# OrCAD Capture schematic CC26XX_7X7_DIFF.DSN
size A3; title: CC2650EM-7ID; rev: 1.2.6
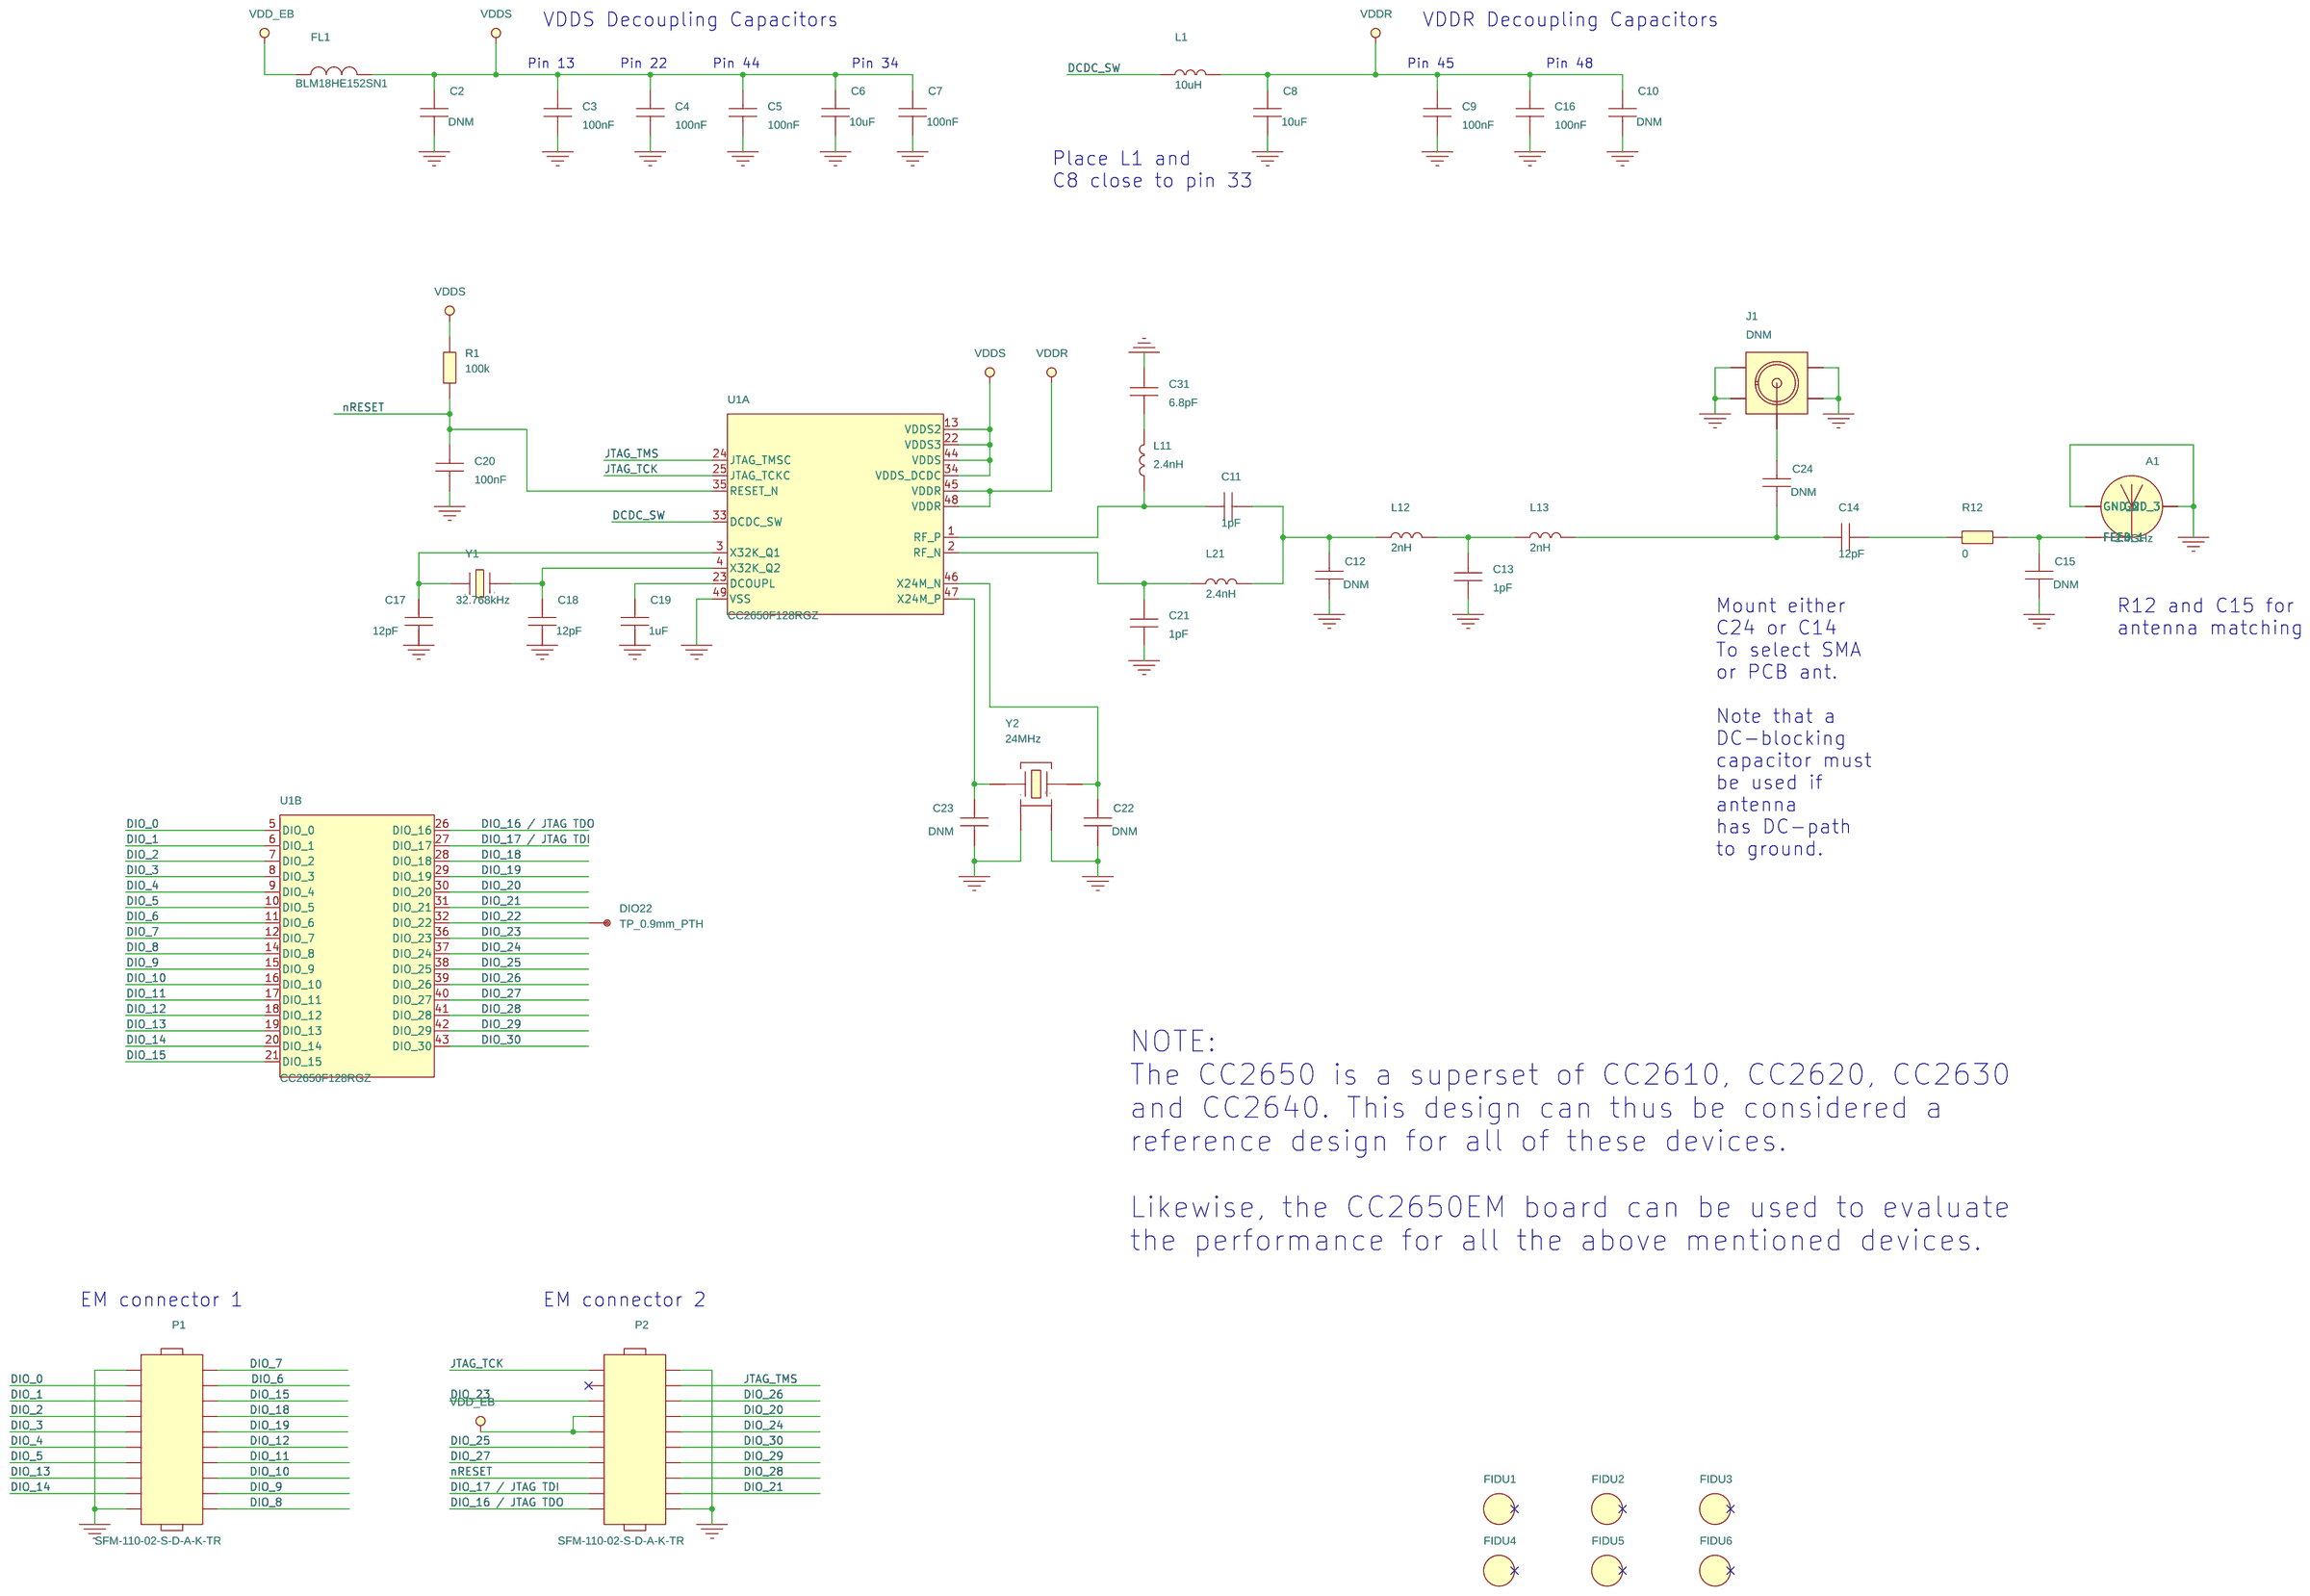
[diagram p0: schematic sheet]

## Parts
A1  2.4GHz  [ANTENNA_DN007AN]
C2  DNM  [CAPC1608X90L]
C3  100nF  [CAPC1005X60L]
C4  100nF  [CAPC1005X60L]
C5  100nF  [CAPC1005X60L]
C6  10uF  [CAPC1608X90N]
C7  100nF  [CAPC1608X90L]
C8  10uF  [CAPC1608X90N]
C9  100nF  [CAPC1005X60L]
C10  DNM  [CAPC1005X60L]
C11  1pF  [CAPC1005X60L]
C12  DNM  [CAPC1005X60L]
C13  1pF  [CAPC1005X60L]
C14  12pF  [CAPC1005X60L]
C15  DNM  [CAPC1005X60L]
C16  100nF  [CAPC1005X60L]
C17  12pF  [CAPC1005X60L]
C18  12pF  [CAPC1005X60L]
C19  1uF  [CAPC1005X60L]
C20  100nF  [CAPC1005X60L]
C21  1pF  [CAPC1005X60L]
C22  DNM  [CAPC1005X60L]
C23  DNM  [CAPC1005X60L]
C24  DNM  [CAPC1005X60L]
C31  6.8pF  [CAPC1005X60L]
DIO22  TP_0.9mm_PTH  [TP150_90H]
FIDU1  FIDU_1MM  [FID100X115]
FIDU2  FIDU_1MM  [FID100X115]
FIDU3  FIDU_1MM  [FID100X115]
FIDU4  FIDU_1MM  [FID100X115]
FIDU5  FIDU_1MM  [FID100X115]
FIDU6  FIDU_1MM  [FID100X115]
FL1  BLM18HE152SN1  [FIL_BLM18HE152SN1DL]
J1  DNM  [HUSTSAN_SMA10V21TGGAN]
L1  10uH  [INDC2012X150L]
L11  2.4nH  [INDC1005X60L]
L12  2nH  [INDC1005X60L]
L13  2nH  [INDC1005X60L]
L21  2.4nH  [INDC1005X60L]
P1  SFM-110-02-S-D-A-K-TR  [SAMTEC_SFM11002AN]
P2  SFM-110-02-S-D-A-K-TR  [SAMTEC_SFM11002AN]
R1  100k  [RESC1005X40L]
R12  0  [RESC1005X40L]
U1  CC2650F128RGZ  [QFNFC50P700X700X80-49CL]  (sections A,B)
Y1  32.768kHz  [XTAL_FC-135N]
Y2  24MHz  [OSCCC250X320X60-4L]

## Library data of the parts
A1 = ANTENNA_DN007: MECHANIC, 2.4GHz INVERTED F ANTENNA, SMD; AutoDoc File: http://notefied-dynamic-precision.com/DB/Apps/Desktop/Item/Object.aspx?id=85542; Budget Currency: N/A; Budget Price: N/A; Datasheet URL 1: http://www.ti.com/lit/er/swrz002d/swrz002d.pdf; Datasheet URL 2: http://www.ti.com/lit/ds/symlink/cc2500.pdf; Definied Quality: INDUSTRIAL; Esd Level: HBM 500V; FPLIST: ANTENNA_DN007N,ANTENNA_DN007AN,; Last Time Buy: N/A; Lead Time: N/A; MPN: DN007; MPN Status: ACTIVE; MSL: N/A; MTBF: N/A; MTBF Standard: N/A; Manufacturer: TEXAS INSTRUMENTS; Max Oper Temp: +85DEGC; Min Oper Temp: -40DEGC; Mounting Type: SMD; NOTE Status: PREFERRED; Old Footprint: ANTENNA_DN007N,ANTENNA_DN007AN; Packing Size: N/A; Packing Type: N/A; Part Number: 13-00347; Part Type: MECHANIC\ANTENNA; Revision: R006; RoHS Status: LEADED; WEIGHT: N/A
C2 = CAPACITOR: CAPACITOR, DO NOT MOUNT, 0603, SMD; ALT_SYMBOLS: CAPC1608X90L,CAPC1608X90M; AutoDoc File: http://notefied-dynamic-precision.com/DB/Apps/Desktop/Item/Object.aspx?id=50475; FPLIST: CAPC1608X90N,CAPC1608X90L,CAPC1608X90M; Old Footprint: CAPC1608X90N,0603; Part Number: 02-01324; Part Type: CAPACITOR\CERAMIC\0603; Revision: R003
C3-C5 C9 C16 C20 = CAPACITOR: CAPACITOR, CERAMIC X7R, 100nF, 6.3V, -10%/+10%, -55DEGC/+125DEGC, 0402, SMD; ALT_SYMBOLS: CAPC1005X60L,CAPC1005X60M; AutoDoc File: http://notefied-dynamic-precision.com/DB/Apps/Desktop/Item/Object.aspx?id=73748; Budget Currency: EUR; Budget Price: 0.003; Datasheet URL 1: http://search.murata.co.jp/Ceramy/image/img/A01X/G101/ENG/GRM155R70J104KA01-01.pdf; Datasheet URL 2: http://search.murata.co.jp/Ceramy/image/img/A01X/G101/ENG/GRM155R70J104KA01-01.pdf; Dielectric Type: X7R; FPLIST: CAPC1005X60N,CAPC1005X60L,CAPC1005X60M; Lead Time: 10; LifeCycle Status: ACTIVE; MPN: GRM155R70J104KA01D; MPN Status: ACTIVE; Manufacturer: MURATA; Max Oper Temp: +125DEGC; Max Tol: +10%; Min Oper Temp: -55DEGC; Min Tol: -10%; Mounting Type: SMD; NOTE Status: PREFERRED; Old Footprint: CAPC1005X60N,0402; PCB Package: 0402; Packing Size: 10000; Packing Type: TAPE_&_REEL; Part Number: 02-02323; Part Type: CAPACITOR\CERAMIC\0402; Revision: R000; RoHS Status: ROHS_COMPLIANT; Rtd Voltage: 6.3V; WEIGHT: 0.0016g
C6 C8 = CAPACITOR: CAPACITOR, CERAMIC X5R, 10uF, 6.3V, -20%/+20%, -55DEGC/+85DEGC, 0603, SMD; ALT_SYMBOLS: CAPC1608X90L,CAPC1608X90M; AutoDoc File: http://notefied-dynamic-precision.com/DB/Apps/Desktop/Item/Object.aspx?id=74686; Budget Currency: EUR; Budget Price: 0.067; Datasheet URL 1: http://search.murata.co.jp/Ceramy/image/img/w_hinm/L0005E.pdf; Datasheet URL 2: http://psearch.murata.com/capacitor/product/GRM188R60J106ME47%23.pdf; Definied Quality: INDUSTRIAL; Dielectric Type: X5R; Esd Level: N/A; FPLIST: CAPC1608X90N,CAPC1608X90L,CAPC1608X90M; Last Time Buy: N/A; Lead Time: 20; MPN: GRM188R60J106ME47D; MPN Status: NRND; MSL: 1; MTBF: N/A; MTBF Standard: N/A; Manufacturer: MURATA; Max Oper Temp: +85DEGC; Max Tol: +20%; Min Oper Temp: -55DEGC; Min Tol: -20%; Mounting Type: SMD; NOTE Status: PREFERRED; PCB Package: 0603; Packing Size: 4000; Packing Type: TAPE_&_REEL; Part Number: 02-02419; Part Type: CAPACITOR\CERAMIC\0603; Revision: R003; RoHS Status: ROHS_COMPLIANT; Rtd Voltage: 6.3V; WEIGHT: 0.0063g
C7 = CAPACITOR: CAPACITOR, CERAMIC X7R, 100nF, 25V, -10%/+10%, -55DEGC/+125DEGC, 0603, SMD; ALT_SYMBOLS: CAPC1608X90L,CAPC1608X90M; AutoDoc File: http://notefied-dynamic-precision.com/DB/Apps/Desktop/Item/Object.aspx?id=72070; Budget Currency: N/A; Budget Price: 0.00391; Cage Code: C0151; Datasheet URL 1: http://search.murata.co.jp/Ceramy/image/img/A01X/G101/ENG/GRM188R71E104KA01-01.pdf; Datasheet URL 2: http://search.murata.co.jp/Ceramy/image/img/A01X/G101/ENG/GRM188R71E104KA01-01.pdf; Dielectric Type: X7R; FPLIST: CAPC1608X90N,CAPC1608X90L,CAPC1608X90M; MPN: GRM188R71E104KA01D; MPN Status: ACTIVE; Manufacturer: MURATA; Max Oper Temp: +125DEGC; Max Tol: +10%; Min Oper Temp: -55DEGC; Min Tol: -10%; Mounting Type: SMD; NOTE Status: PREFERRED; Old Footprint: CAPC1608X90N,0603; PCB Package: 0603; Packing Size: 4000; Packing Type: TAPE_&_REEL; Part Number: 02-01992; Part Type: CAPACITOR\CERAMIC\0603; Revision: R000; RoHS Status: ROHS_COMPLIANT; Rtd Voltage: 25V; WEIGHT: 0.0063g
C10 C12 C15 C22-C24 = CAPACITOR: CAPACITOR, CERAMIC, N/A VALUE, -55DEGC/+125DEGC, 0402, SMD; ALT_SYMBOLS: CAPC1005X60L,CAPC1005X60M; AutoDoc File: http://notefied-dynamic-precision.com/DB/Apps/Desktop/Item/Object.aspx?id=84862; Budget Currency: USD; Budget Price: 0.00589; FPLIST: CAPC1005X60N,CAPC1005X60L,CAPC1005X60M; MPN: CAPACITOR_0402_DNM_N/A_M; MPN Status: ACTIVE; Manufacturer: Manufacturer selection; Max Oper Temp: +125DEGC; Min Oper Temp: -55DEGC; Mounting Type: SMD; NOTE Status: PREFERRED; Old Footprint: CAPC1005X60N; PCB Package: 0402; Packing Size: 10000; Packing Type: TAPE_&_REEL; Part Number: 02-04164; Part Type: CAPACITOR\CERAMIC\0402; Revision: R000; RoHS Status: PART NOT KNOWN
C11 C13 C21 = CAPACITOR: CAPACITOR, CERAMIC C0G/NP0, 1pF, 50V, -0.25pF/ +0.25pF, -55DEGC/+125DEGC, 0402, SMD; ALT_SYMBOLS: CAPC1005X60L,CAPC1005X60M; AutoDoc File: http://notefied-dynamic-precision.com/DB/Apps/Desktop/Item/Object.aspx?id=87790; Budget Currency: EUR; Budget Price: 0.003; Datasheet URL 2: http://psearch.murata.com/capacitor/product/GRM1555C1H1R0CA01%23.pdf; Dielectric Type: C0G/NP0; FPLIST: CAPC1005X60N,CAPC1005X60L,CAPC1005X60M; Lead Time: 12; MPN: GRM1555C1H1R0CA01D; MPN Status: ACTIVE; Manufacturer: MURATA; Max Oper Temp: +125DEGC; Max TC: +30PPM/DEGC; Max Tol: +0.25pF; Min Oper Temp: -55DEGC; Min TC: -30PPM/DEGC; Min Tol: -0.25pF; Mounting Type: SMD; NOTE Status: PREFERRED; Old Footprint: CAPC1005X60N; PCB Package: 0402; Packing Size: 10000; Packing Type: TAPE_&_REEL; Part Number: 02-04672; Part Type: CAPACITOR\CERAMIC\0402; Revision: R001; RoHS Status: ROHS_COMPLIANT; Rtd Voltage: 50V; WEIGHT: 1.6mg
C14 = CAPACITOR: CAPACITOR, CERAMIC C0G/NP0, 12pF, 50V, -5%/+5%, -55DEGC/+125DEGC, 0402, SMD; ALT_SYMBOLS: CAPC1005X60L,CAPC1005X60M; AutoDoc File: http://notefied-dynamic-precision.com/DB/Apps/Desktop/Item/Object.aspx?id=84867; Budget Currency: EUR; Budget Price: 0.004; Datasheet URL 1: http://search.murata.co.jp/Ceramy/image/img/A01X/G101/ENG/GRM1555C1H120JA01-01.pdf; Datasheet URL 2: http://search.murata.co.jp/Ceramy/image/img/A01X/G101/ENG/GRM1555C1H120JA01-01.pdf; Dielectric Type: C0G/NP0; FPLIST: CAPC1005X60N,CAPC1005X60L,CAPC1005X60M; Lead Time: 12; MPN: GRM1555C1H120JA01D; MPN Status: ACTIVE; Manufacturer: MURATA; Max Oper Temp: +125DEGC; Max TC: +30PPM/DEGC; Max Tol: +5%; Min Oper Temp: -55DEGC; Min TC: -30PPM/DEGC; Min Tol: -5%; Mounting Type: SMD; NOTE Status: PREFERRED; Old Footprint: CAPC1005X60N; PCB Package: 0402; Packing Size: 10000; Packing Type: TAPE_&_REEL; Part Number: 02-04168; Part Type: CAPACITOR\CERAMIC\0402; Revision: R000; RoHS Status: ROHS_COMPLIANT; Rtd Voltage: 50V; WEIGHT: 0.0016g
C17 C18 = CAPACITOR: CAPACITOR, CERAMIC C0G/NP0, 12pF, 50V, -5%/+5%, -55DEGC/+125DEGC, 0402, SMD; ALT_SYMBOLS: CAPC1005X60L,CAPC1005X60M; AutoDoc File: http://notefied-dynamic-precision.com/DB/Apps/Desktop/Item/Object.aspx?id=80123; Budget Currency: USD; Budget Price: 0.00589; Datasheet URL 1: N/A; Datasheet URL 2: N/A; Definied Quality: INDUSTRIAL; Dielectric Type: C0G/NP0; Esd Level: N/A; FPLIST: CAPC1005X60N,CAPC1005X60L,CAPC1005X60M; Last Time Buy: N/A; Lead Time: N/A; LifeCycle Status: ACTIVE; MPN: CAPACITOR_0402_12pF_C0G/NP0_M_+/-5%_50V; MPN Status: ACTIVE; MSL: N/A; MTBF: N/A; MTBF Standard: N/A; Manufacturer: MANUFACTURER SELECTION; Max Oper Temp: +125DEGC; Max Tol: +5%; Min Oper Temp: -55DEGC; Min Tol: -5%; Mounting Type: SMD; NOTE Status: PREFERRED; Old Footprint: CAPC1005X60N; PCB Package: 0402; Packing Size: 10000; Packing Type: TAPE_&_REEL; Part Number: 02-03030; Part Type: CAPACITOR\CERAMIC\0402; Revision: R000; RoHS Status: ROHS_COMPLIANT; Rtd Voltage: 50V; WEIGHT: N/A
C19 = CAPACITOR: CAPACITOR, CERAMIC X5R, 1uF, 10V, -10%/+10%, -55DEGC/+85DEGC, 0402, SMD; ALT_SYMBOLS: CAPC1005X60L,CAPC1005X60M; AutoDoc File: http://notefied-dynamic-precision.com/DB/Apps/Desktop/Item/Object.aspx?id=74236; Budget Currency: EUR; Budget Price: 0.015; Datasheet URL 1: http://search.murata.co.jp/Ceramy/image/img/w_hinm/L0005E.pdf; Datasheet URL 2: http://psearch.murata.com/capacitor/product/GRM155R61A105KE15%23.pdf; Definied Quality: INDUSTRIAL; Dielectric Type: X5R; Esd Level: N/A; FPLIST: CAPC1005X60N,CAPC1005X60L,CAPC1005X60M; Last Time Buy: N/A; Lead Time: 14; MPN: GRM155R61A105KE15D; MPN Status: ACTIVE; MSL: 1; MTBF: N/A; MTBF Standard: N/A; Manufacturer: MURATA; Max Oper Temp: +85DEGC; Max Tol: +10%; Min Oper Temp: -55DEGC; Min Tol: -10%; Mounting Type: SMD; NOTE Status: PREFERRED; Old Footprint: CAPC1005X60N,0402; PCB Package: 0402; Packing Size: 10000; Packing Type: TAPE_&_REEL; Part Number: 02-02381; Part Type: CAPACITOR\CERAMIC\0402; Revision: R002; RoHS Status: ROHS_COMPLIANT; Rtd Voltage: 10V; WEIGHT: 0.0016g
C31 = CAPACITOR: CAPACITOR, CERAMIC C0G/NP0, 6.8pF, 50V, -0.25pF, +0.25pF, -55DEGC/+125DEGC, 0402, SMD; ALT_SYMBOLS: CAPC1005X60L,CAPC1005X60M; AutoDoc File: http://notefied-dynamic-precision.com/DB/Apps/Desktop/Item/Object.aspx?id=84868; Budget Currency: EUR; Budget Price: 0.004; Datasheet URL 1: http://search.murata.co.jp/Ceramy/image/img/A01X/G101/ENG/GRM1555C1H6R8CA01-01.pdf; Datasheet URL 2: http://search.murata.co.jp/Ceramy/image/img/A01X/G101/ENG/GRM1555C1H6R8CA01-01.pdf; Dielectric Type: C0G/NP0; FPLIST: CAPC1005X60N,CAPC1005X60L,CAPC1005X60M; Lead Time: 12; MPN: GRM1555C1H6R8CA01D; MPN Status: ACTIVE; Manufacturer: MURATA; Max Oper Temp: +125DEGC; Max TC: +30PPM/DEGC; Max Tol: +0.25pF; Min Oper Temp: -55DEGC; Min TC: -30PPM/DEGC; Min Tol: -0.25pF; Mounting Type: SMD; NOTE Status: PREFERRED; Old Footprint: CAPC1005X60N; PCB Package: 0402; Packing Size: 10000; Packing Type: TAPE_&_REEL; Part Number: 02-04169; Part Type: CAPACITOR\CERAMIC\0402; Revision: R000; RoHS Status: ROHS_COMPLIANT; Rtd Voltage: 50V; WEIGHT: 0.0016g
DIO22 = TEST_POINT: NON COMPONENT, TEST POINT 0.9mm, PTH; AutoDoc File: https://notefied-dynamic-precision.com/NotefiedWebServices/AutoDocs.aspx?itemid=84966; FPLIST: TP150_90H,; Part Number: 19-00299; Part Type: NON_COMPONENT\TEST_POINT; Revision: R001
FIDU1-FIDU6 = FIDMARK: FIDUCIAL MARK, ROUND 1MM; AutoDoc File: https://notefied-dynamic-precision.com/NotefiedWebServices/AutoDocs.aspx?itemid=74548; Part Number: 19-00111; Part Type: NON_COMPONENT\FIDUCIAL; Revision: R001
FL1 = FILTER_2PIN: FILTER, EMI, 1500@100MHz, -55DEGC/+125DEGC, 0603, SMD; ALT_SYMBOLS: FIL_BLM18HE152SN1DL,FIL_BLM18HE152SN1DM; AutoDoc File: http://notefied-dynamic-precision.com/DB/Apps/Desktop/Item/Object.aspx?id=85575; Budget Currency: EUR; Budget Price: 0.085; Datasheet URL 1: http://search.murata.co.jp/Ceramy/image/img/PDF/ENG/L0110S0101BLM18H.pdf; Datasheet URL 2: http://search.murata.co.jp/Ceramy/image/img/PDF/ENG/L0110S0101BLM18H.pdf; FPLIST: FIL_BLM18HE152SN1DN,FIL_BLM18HE152SN1DL,FIL_BLM18HE152SN1DM; Impedance: 1500@100MHz; Lead Time: 26; MPN: BLM18HE152SN1D; MPN Status: ACTIVE; Manufacturer: MURATA; Max Oper Temp: +125DEGC; Max Tol: +25%; Min Oper Temp: -55DEGC; Min Tol: -25%; Mounting Type: SMD; NOTE Status: PREFERRED; Old Footprint: FIL_BLM18HE152SN1DN; PCB Package: 0603; Packing Size: 4000; Packing Type: TAPE_&_REEL; Part Number: 04-00470; Part Type: FILTER\EMI\0603; Revision: R001; RoHS Status: ROHS_COMPLIANT; Rtd Current: 0.5A; WEIGHT: 0.006g
J1 = CONN_COAX_1+4: CONNECTOR, COAX RF, STRAIGHT, FEMALE, 1 PIN, SMD; ALT_SYMBOLS: HUSTSAN_SMA10V21TGGL,HUSTSAN_SMA10V21TGGM; AutoDoc File: http://notefied-dynamic-precision.com/DB/Apps/Desktop/Item/Object.aspx?id=84956; Budget Currency: USD; Budget Price: 1.21; Datasheet URL 1: http://www.hustsan.com.tw/uploaddir/product/SMA-10V21.pdf; Datasheet URL 2: http://www.hustsan.com.tw/uploaddir/product/SMA-10V21.pdf; FPLIST: HUSTSAN_SMA10V21TGGAN,HUSTSAN_SMA10V21TGGN; Lead Time: 5; MPN: SMA-10V21-TGG; MPN Status: ACTIVE; MSL: N/A; Manufacturer: HUS-TSAN; Mounting Type: SMD; NOTE Status: PREFERRED; No Of Pos: 1; Old Footprint: HUSTSAN_SMA10V21TGGAN,HUSTSAN_SMA10V21TGGN; Packing Size: 350; Packing Type: TAPE_&_REEL; Part Number: 06-02188; Part Type: CONNECTOR\COAX; Revision: R003; RoHS Status: N/A; WEIGHT: N/A
L1 = INDUCTOR: INDUCTOR, CHIP, 10uH, -20%/+20%, 0.11A, -40DEGC/+85DEGC, 0805, SMD; ALT_SYMBOLS: INDC2012X150L,INDC2012X150M; AutoDoc File: http://notefied-dynamic-precision.com/DB/Apps/Desktop/Item/Object.aspx?id=84960; Budget Currency: USD; Budget Price: 0.04; Datasheet URL 1: http://www.yuden.co.jp/us/product/pdf/mlci_all_e.pdf; Datasheet URL 2: http://www.yuden.co.jp/us/product/pdf/mlci_all_e.pdf; FPLIST: INDC2012X150N,INDC2012X150L,INDC2012X150M; Frequency: 24MHz; MPN: CKS2125100M-T; MPN Status: ACTIVE; Manufacturer: TAIYO YUDEN; Max Oper Temp: +85DEGC; Max Tol: +20%; Min Oper Temp: -40DEGC; Min Tol: -20%; Mounting Type: SMD; NOTE Status: PREFERRED; Old Footprint: INDC2012X150N; PCB Package: 0805; Packing Size: 4000; Packing Type: TAPE_&_REEL; Part Number: 03-06514; Part Type: INDUCTOR\CHIP\0805; Revision: R001; RoHS Status: ROHS_COMPLIANT; Rtd Current: 0.11A
L11 L21 = INDUCTOR: INDUCTOR, CHIP, 2.4nH, -0.3nH/+0.3nH, 0.3A, -55DEGC/+125DEGC, 0402, SMD; ALT_SYMBOLS: INDC1005X60M,INDC1005X60L; AutoDoc File: http://notefied-dynamic-precision.com/DB/Apps/Desktop/Item/Object.aspx?id=86086; Budget Currency: EUR; Budget Price: 0.021; Datasheet URL 1: http://search.murata.co.jp/Ceramy/image/img/PDF/ENG/L0075S0083LQG15HN.pdf; Datasheet URL 2: http://search.murata.co.jp/Ceramy/image/img/PDF/ENG/L0075S0083LQG15HN.pdf; FPLIST: INDC1005X60N,INDC1005X60M,INDC1005X60L; Frequency: 6GHz; Lead Time: 7; MPN: LQG15HN2N4S02D; MPN Status: ACTIVE; Manufacturer: MURATA; Max Oper Temp: +125DEGC; Max Tol: +0.3nH; Min Oper Temp: -55DEGC; Min Tol: -0.3nH; Mounting Type: SMD; NOTE Status: PREFERRED; Old Footprint: INDC1005X60N; PCB Package: 0402; Packing Size: 10000; Packing Type: TAPE_&_REEL; Part Number: 03-06554; Part Type: INDUCTOR\CHIP\0402; Resistance: 0.16; Revision: R001; RoHS Status: ROHS_COMPLIANT; Rtd Current: 0.3A; WEIGHT: 0.001g
L12 L13 = INDUCTOR: INDUCTOR, CHIP, 2nH, -0.3nH/ +0.3nH, 0.3A, -55DEGC/+125DEGC, 0402, SMD; ALT_SYMBOLS: INDC1005X60L,INDC1005X60M; AutoDoc File: http://notefied-dynamic-precision.com/DB/Apps/Desktop/Item/Object.aspx?id=85431; Budget Currency: EUR; Budget Price: 0.021; Datasheet URL 1: http://search.murata.co.jp/Ceramy/image/img/PDF/ENG/L0075S0083LQG15HS.pdf; Datasheet URL 2: http://search.murata.co.jp/Ceramy/image/img/PDF/ENG/L0075S0083LQG15HS.pdf; FPLIST: INDC1005X60N,INDC1005X60L,INDC1005X60M; Frequency: 6GHz; Lead Time: 9; MPN: LQG15HS2N0S02D; MPN Status: ACTIVE; Manufacturer: MURATA; Max Oper Temp: +125DEGC; Max Tol: +0.3nH; Min Oper Temp: -55DEGC; Min Tol: -0.3nH; Mounting Type: SMD; NOTE Status: PREFERRED; Old Footprint: INDC1005X60N; PCB Package: 0402; Packing Size: 10000; Packing Type: TAPE_&_REEL; Part Number: 03-06525; Part Type: INDUCTOR\CHIP\0402; Revision: R001; RoHS Status: ROHS_COMPLIANT; Rtd Current: 0.3A; WEIGHT: 0.001g
P1 P2 = CONN_HEADER_2X10_P_S: CONNECTOR, HEADER, FEMALE, STRAIGHT, 2 ROWS, 20 PINS, PITCH 1.27mm, SMD; Alt IPC Footprints: SAMTEC_SFM11002AL,SAMTEC_SFM11002AM; AutoDoc File: https://notefied-dynamic-precision.com/NotefiedWebServices/AutoDocs.aspx?itemid=85603; Datasheet URL 1: http://www.samtec.com/ProductInformation/TechnicalSpecifications/CatalogPages.aspx?series=SFM; Datasheet URL 2: http://www.samtec.com/documents/webfiles/cpdf/SFM-1XX-XX-XX-S-XX-MKT1.pdf; MPN: SFM-110-02-SM-D-A-K-TR; MPN Status: ACTIVE; Manufacturer: SAMTEC; Max Oper Temp: +125DEGC; Min Oper Temp: -55DEGC; Mounting Type: SMD; NOTE Status: PREFERRED; No Of Pos: 20; No Of Rows: 2; Packing Size: 125; Packing Type: TAPE_&_REEL; Part Number: 06-02251; Part Type: CONNECTOR\HEADER; Pitch: 1.27mm; Revision: R001; RoHS Status: ROHS_COMPLIANT
R1 = RESISTOR: RESISTOR, THICK FILM, 100k, -1%/+1%, 0.063W, 50V, -55DEGC/+155DEGC, 0402, SMD; ALT_SYMBOLS: RESC1005X40L,RESC1005X40M; AutoDoc File: http://notefied-dynamic-precision.com/DB/Apps/Desktop/Item/Object.aspx?id=76892; Budget Currency: USD; Budget Price: 0.00244; Datasheet URL 1: N/A; Datasheet URL 2: N/A; Definied Quality: INDUSTRIAL; Esd Level: N/A; FPLIST: RESC1005X40N,RESC1005X40L,RESC1005X40M; Last Time Buy: N/A; Lead Time: N/A; LifeCycle Status: ACTIVE; MPN: RESISTOR_0402_100k_+/-1%_50V_0.063W_M_+/-100PPM; MPN Status: ACTIVE; MSL: N/A; MTBF: N/A; MTBF Standard: N/A; Manufacturer: MANUFACTURER SELECTION; Max Oper Temp: +155DEGC; Max TC: +100PPM/DEGC; Max Tol: +1%; Min Oper Temp: -55DEGC; Min TC: -100PPM/DEGC; Min Tol: -1%; Mounting Type: SMD; NOTE Status: PREFERRED; Old Footprint: RESC1005X40N; PCB Package: 0402; Packing Size: 10000; Packing Type: TAPE_&_REEL; Part Number: 01-12837; Part Type: RESISTOR\0402\PRECISION; Resistor Type: THICK FILM; Revision: R002; RoHS Status: ROHS_COMPLIANT; Rtd Power: 0.063W; Rtd Voltage: 50V; WEIGHT: N/A
R12 = RESISTOR: RESISTOR, JUMPER, -55DEGC/+155DEGC, 0402, SMD; ALT_SYMBOLS: RESC1005X40L,RESC1005X40M; AutoDoc File: http://notefied-dynamic-precision.com/DB/Apps/Desktop/Item/Object.aspx?id=47668; Budget Currency: EUR; Budget Price: 0.016; Datasheet URL 1: http://www.koaspeer.com/pdfs/Appendix_A.pdf; Datasheet URL 2: http://www.koaspeer.com/catimages/Products/RK73Z/RK73Z.pdf; Definied Quality: INDUSTRIAL; Esd Level: N/A; FPLIST: RESC1005X40N,RESC1005X40L,RESC1005X40M; Last Time Buy: N/A; Lead Time: 10; LifeCycle Status: ACTIVE; MPN: RK73Z1ETTP; MPN Status: ACTIVE; MSL: 1; MTBF: N/A; MTBF Standard: N/A; Manufacturer: KOA SPEER; Max Oper Temp: +155DEGC; Min Oper Temp: -55DEGC; Mounting Type: SMD; NOTE Status: PREFERRED; Old Footprint: RESC1005X40N,0402; PCB Package: 0402; Packing Size: 10000; Packing Type: TAPE_&_REEL; Part Number: 01-01784; Part Type: RESISTOR\JUMPER\0402; Revision: R002; RoHS Status: ROHS_COMPLIANT; Rtd Current: 1A; WEIGHT: 0.00068g
U1 = IC_RF_CC26XX_QFN48_V2: IC, DIGITAL, 2.4GHZ SIMPLELINK WIRELESS MCU, PITCH 0,5MM, QFN48, SMD; ALT_SYMBOLS: QFNFC50P700X700X80-49CL,QFNFC50P700X700X80-49CM; AutoDoc File: http://notefied-dynamic-precision.com/DB/Apps/Desktop/Item/Object.aspx?id=88778; Budget Currency: N/A; Budget Price: N/A; Datasheet URL 1: N/A; Datasheet URL 2: www.ti.com; Definied Quality: COMMERCIAL; Esd Level: N/A; FPLIST: QFNFC50P700X700X80-49CN,QFNFC50P700X700X80-49CL,QFNFC50P700X700X80-49CM; Last Time Buy: N/A; Lead Time: N/A; MPN: CC2650F128RGZT; MPN Status: PRELIMINARY; MSL: N/A; MTBF: N/A; MTBF Standard: N/A; Manufacturer: TEXAS INSTRUMENTS; Max Oper Temp: +85DEGC; Min Oper Temp: -40DEGC; Mounting Type: SMD; NOTE Status: PREFERRED; Old Footprint: QFNFC50P700X700X80-49CN; PCB Package: QFN48; Packing Size: 2500; Packing Type: TAPE_&_REEL; Part Number: 18-28499; Part Type: IC\DIGITAL\WIRELESS; Revision: R003; RoHS Status: ROHS_COMPLIANT; Rtd Voltage: 3.8V; WEIGHT: N/A
Y1 = CRYSTAL: CRYSTAL, RESONATOR, 32.768kHz, -20PPM/+20PPM, -40DEGC/+85DEGC, SMD; ALT_SYMBOLS: XTAL_FC-135L,XTAL_FC-135M; AutoDoc File: http://notefied-dynamic-precision.com/DB/Apps/Desktop/Item/Object.aspx?id=91966; Budget Currency: USD; Budget Price: 1.25375; Capacitance: 7pF; Datasheet URL 1: http://www.eea.epson.com/portal/pls/portal/docs/1/1525528.PDF; Datasheet URL 2: http://www.eea.epson.com/portal/pls/portal/docs/1/1525451.PDF; Definied Quality: INDUSTRIAL; Esd Level: N/A; FPLIST: XTAL_FC-135N,XTAL_FC-135L,XTAL_FC-135M; Last Time Buy: N/A; Lead Time: 10; MPN: FC-135 32.7680KA-AG0; MPN Status: ACTIVE; MSL: N/A; MTBF: N/A; MTBF Standard: N/A; Manufacturer: EPSON; Max Oper Temp: +85DEGC; Max Tol: +20PPM; Min Oper Temp: -40DEGC; Min Tol: -20PPM; Mounting Type: SMD; NOTE Status: PREFERRED; Packing Size: 1000; Packing Type: TAPE_&_REEL; Part Number: 12-00546; Part Type: CRYSTAL\OSCILLATOR\MEMS; Revision: R001; RoHS Status: ROHS_COMPLIANT; WEIGHT: N/A
Y2 = XTAL_4PIN_S: CRYSTAL, CRYSTAL OSCILLATOR, 24MHz, -15PPM/DEGC/+15PPM/DEGC, -40DEGC/+85DEGC, SMD; ALT_SYMBOLS: OSCCC250X320X60-4L,OSCCC250X320X60-4M; AutoDoc File: http://notefied-dynamic-precision.com/DB/Apps/Desktop/Item/Object.aspx?id=96738; Budget Currency: EUR; Budget Price: 0.256; Capacitance: 9pF; Datasheet URL 1: http://www.eea.epson.com/portal/pls/portal/docs/1/1721495.PDF; Datasheet URL 2: http://www.epsondevice.com/docs/qd/en/DownloadServlet?id=ID000658; FPLIST: OSCCC250X320X60-4N,OSCCC250X320X60-4L,OSCCC250X320X60-4M; Lead Time: 12; MPN: TSX-3225 24.0000MF15X-AC3; MPN Status: ACTIVE; Manufacturer: EPSON; Max Oper Temp: +85DEGC; Max TC: +15PPM/DEGC; Max Tol: +10PPM; Min Oper Temp: -40DEGC; Min TC: -15PPM/DEGC; Min Tol: -10PPM; Mounting Type: SMD; NOTE Status: PREFERRED; Old Footprint: OSCCC250X320X60-4N; Packing Size: 250; Packing Type: TAPE_&_REEL; Part Number: 12-00757; Part Type: CRYSTAL\OSCILLATOR; Revision: R001; RoHS Status: ROHS_COMPLIANT

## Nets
GND: A1.2(GND) A1.3(GND) C2.2 C3.2 C4.2 C5.2 C6.2 C7.2 C8.2 C9.2 C10.2 C12.2 C13.1 C15.2 C16.2 C17.2 C18.2 C19.2 C20.2 C21.1 C22.2 C23.2 C31.2 J1.2 J1.3 J1.4 J1.5 P1.1 P1.19 P2.2 P2.20 U1.49(VSS) Y2.2 Y2.4
VDD_EB: FL1.2 P2.7 P2.9
VDDR: C8.1 C9.1 C10.1 C16.1 L1.2 U1.45(VDDR) U1.48(VDDR)
VDDS: C2.1 C3.1 C4.1 C5.1 C6.1 C7.1 FL1.1 R1.2 U1.13(VDDS2) U1.22(VDDS3) U1.34(VDDS_DCDC) U1.44(VDDS)
DCDC_SW: L1.1 U1.33(DCDC_SW)
DIO_0: P1.3 U1.5(DIO_0)
DIO_1: P1.5 U1.6(DIO_1)
DIO_2: P1.7 U1.7(DIO_2)
DIO_3: P1.9 U1.8(DIO_3)
DIO_4: P1.11 U1.9(DIO_4)
DIO_5: P1.13 U1.10(DIO_5)
DIO_6: P1.4 U1.11(DIO_6)
DIO_7: P1.2 U1.12(DIO_7)
DIO_8: P1.20 U1.14(DIO_8)
DIO_9: P1.18 U1.15(DIO_9)
DIO_10: P1.16 U1.16(DIO_10)
DIO_11: P1.14 U1.17(DIO_11)
DIO_12: P1.12 U1.18(DIO_12)
DIO_13: P1.15 U1.19(DIO_13)
DIO_14: P1.17 U1.20(DIO_14)
DIO_15: P1.6 U1.21(DIO_15)
DIO_16 / JTAG TDO: P2.19 U1.26(DIO_16)
DIO_17 / JTAG TDI: P2.17 U1.27(DIO_17)
DIO_18: P1.8 U1.28(DIO_18)
DIO_19: P1.10 U1.29(DIO_19)
DIO_20: P2.8 U1.30(DIO_20)
DIO_21: P2.18 U1.31(DIO_21)
DIO_22: DIO22.1 U1.32(DIO_22)
DIO_23: P2.5 U1.36(DIO_23)
DIO_24: P2.10 U1.37(DIO_24)
DIO_25: P2.11 U1.38(DIO_25)
DIO_26: P2.6 U1.39(DIO_26)
DIO_27: P2.13 U1.40(DIO_27)
DIO_28: P2.16 U1.41(DIO_28)
DIO_29: P2.14 U1.42(DIO_29)
DIO_30: P2.12 U1.43(DIO_30)
JTAG_TCK: P2.1 U1.25(JTAG_TCKC)
JTAG_TMS: P2.4 U1.24(JTAG_TMSC)
nRESET: C20.1 P2.15 R1.1 U1.35(RESET_N)
N310466: C23.1 U1.47(X24M_P) Y2.1
N310868: C22.1 U1.46(X24M_N) Y2.3
N314427: C21.2 L21.1 U1.2(RF_N)
N314470: C11.1 L11.1 U1.1(RF_P)
N314514: C31.1 L11.2
N314764: C11.2 C12.1 L12.1 L21.2
N315193: C13.2 L12.2 L13.1
N316022: A1.1(FEED) C15.1 R12.1
N316040: C24.1 J1.1
N316649: C19.1 U1.23(DCOUPL)
N316919: C17.1 U1.3(X32K_Q1) Y1.1
N316932: C18.1 U1.4(X32K_Q2) Y1.2
N334495: C14.1 C24.2 L13.2
N356130: C14.2 R12.2

Not connected (* = marked no-connect by the designer): FIDU1 1*; FIDU2 1*; FIDU3 1*; FIDU4 1*; FIDU5 1*; FIDU6 1*; P2 3*

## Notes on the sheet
- VDDS Decoupling Capacitors
- VDDR Decoupling Capacitors
- Pin 13
- Pin 22
- Pin 44
- Pin 34
- Pin 45
- Pin 48
- Place L1 and
  C8 close to pin 33
- Mount either
  C24 or C14
  To select SMA
  or PCB ant.
  Note that a
  DC-blocking
  capacitor must
  be used if
  antenna
  has DC-path
  to ground.
- R12 and C15 for
  antenna matching
- NOTE:
  The CC2650 is a superset of CC2610, CC2620, CC2630
  and CC2640. This design can thus be considered a
  reference design for all of these devices.
  Likewise, the CC2650EM board can be used to evaluate
  the performance for all the above mentioned devices.
- EM connector 1
- EM connector 2
